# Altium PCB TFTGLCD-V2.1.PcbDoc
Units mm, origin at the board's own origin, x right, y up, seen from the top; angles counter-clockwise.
Board outline 98 x 57 mm, 2 copper layers (Top Layer, Bottom Layer), stack 1.571 mm thick; 48 components, 66 nets, 277 pads, 54 vias.
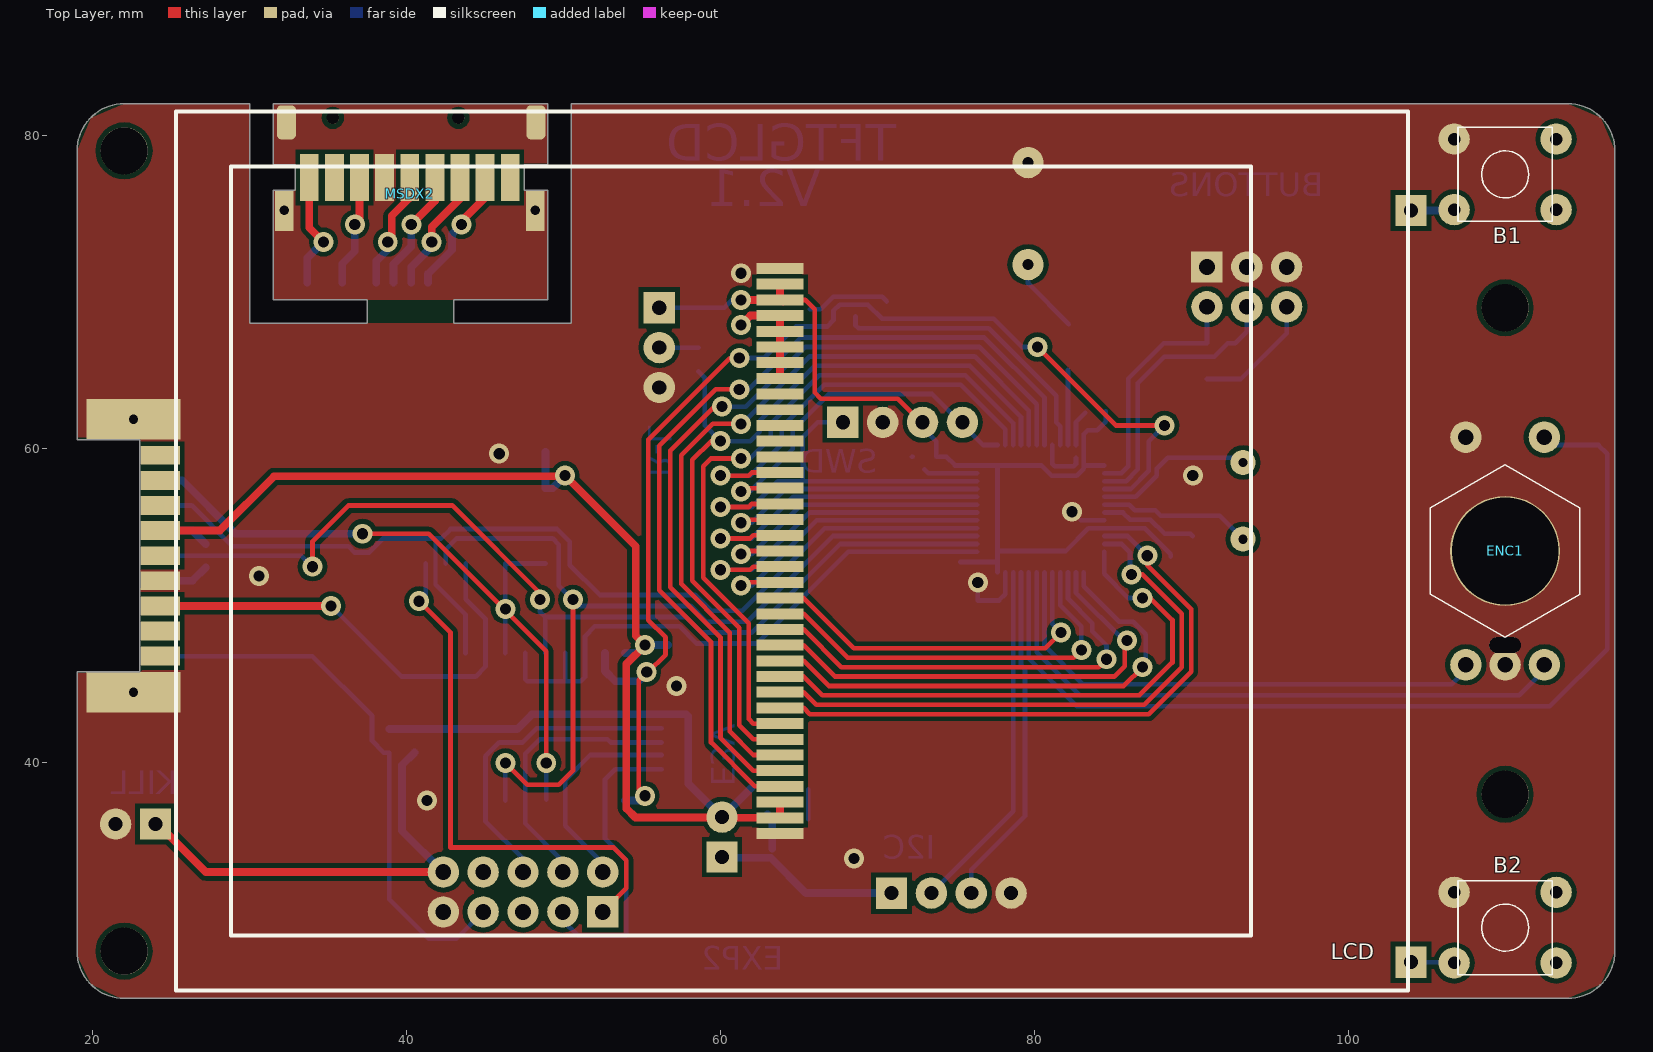
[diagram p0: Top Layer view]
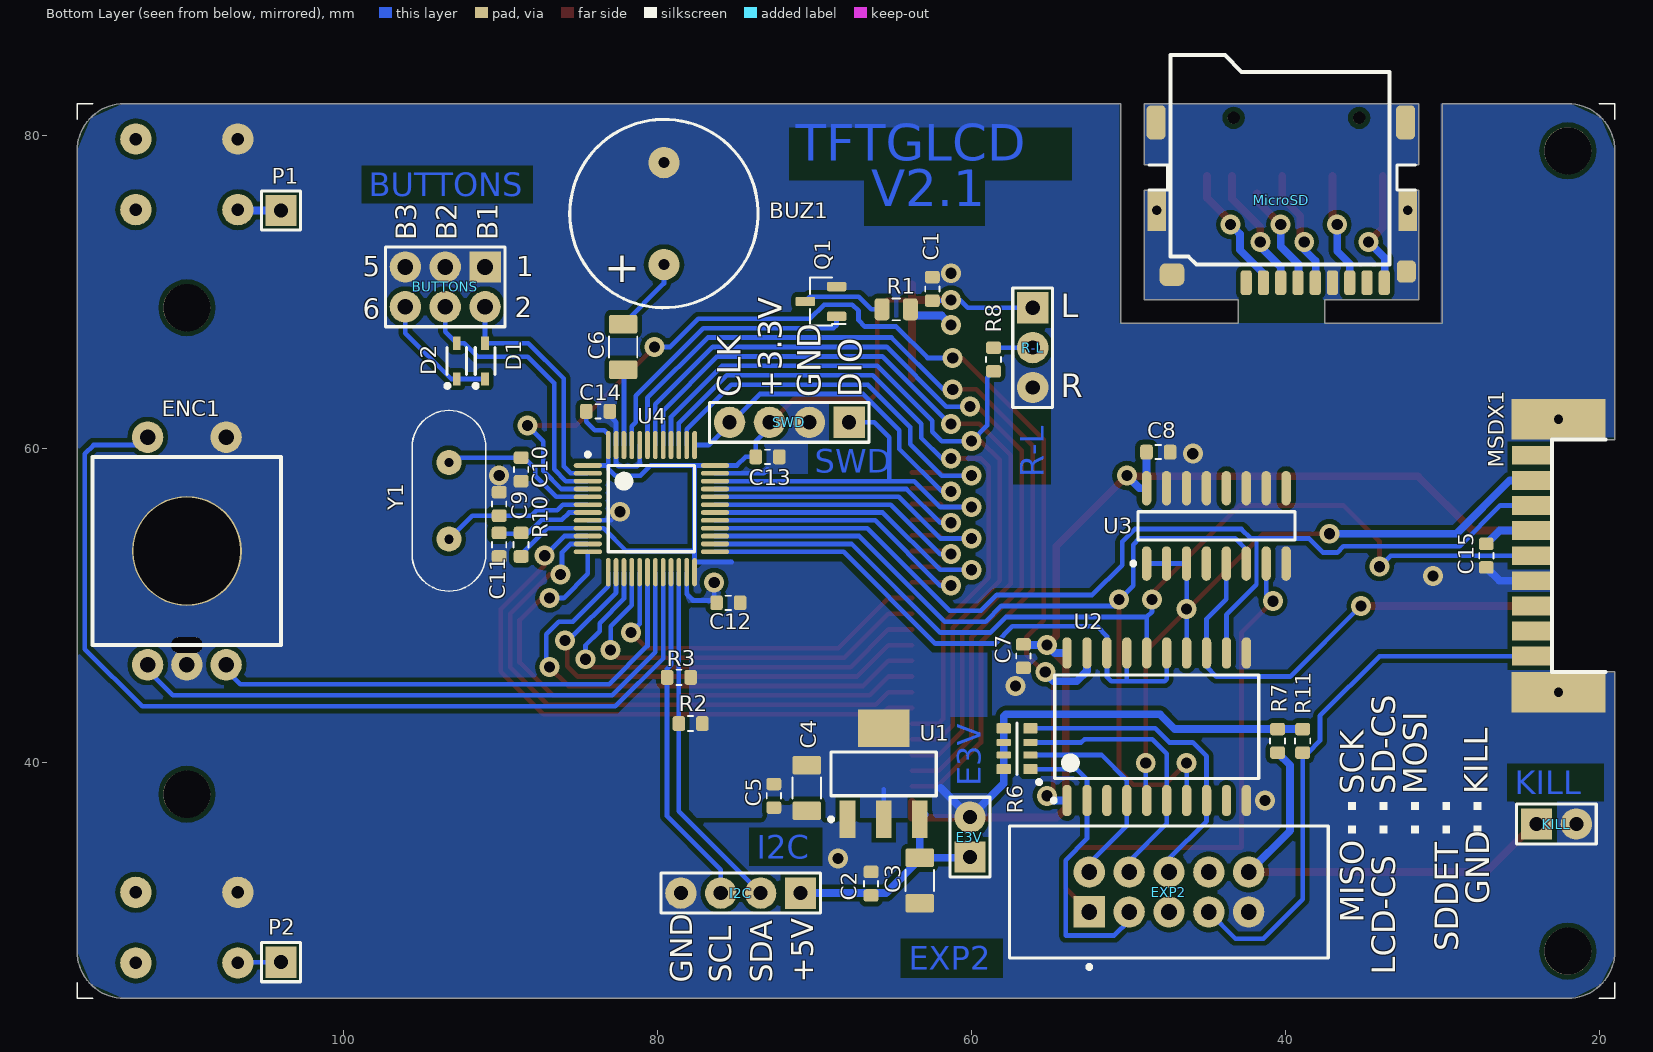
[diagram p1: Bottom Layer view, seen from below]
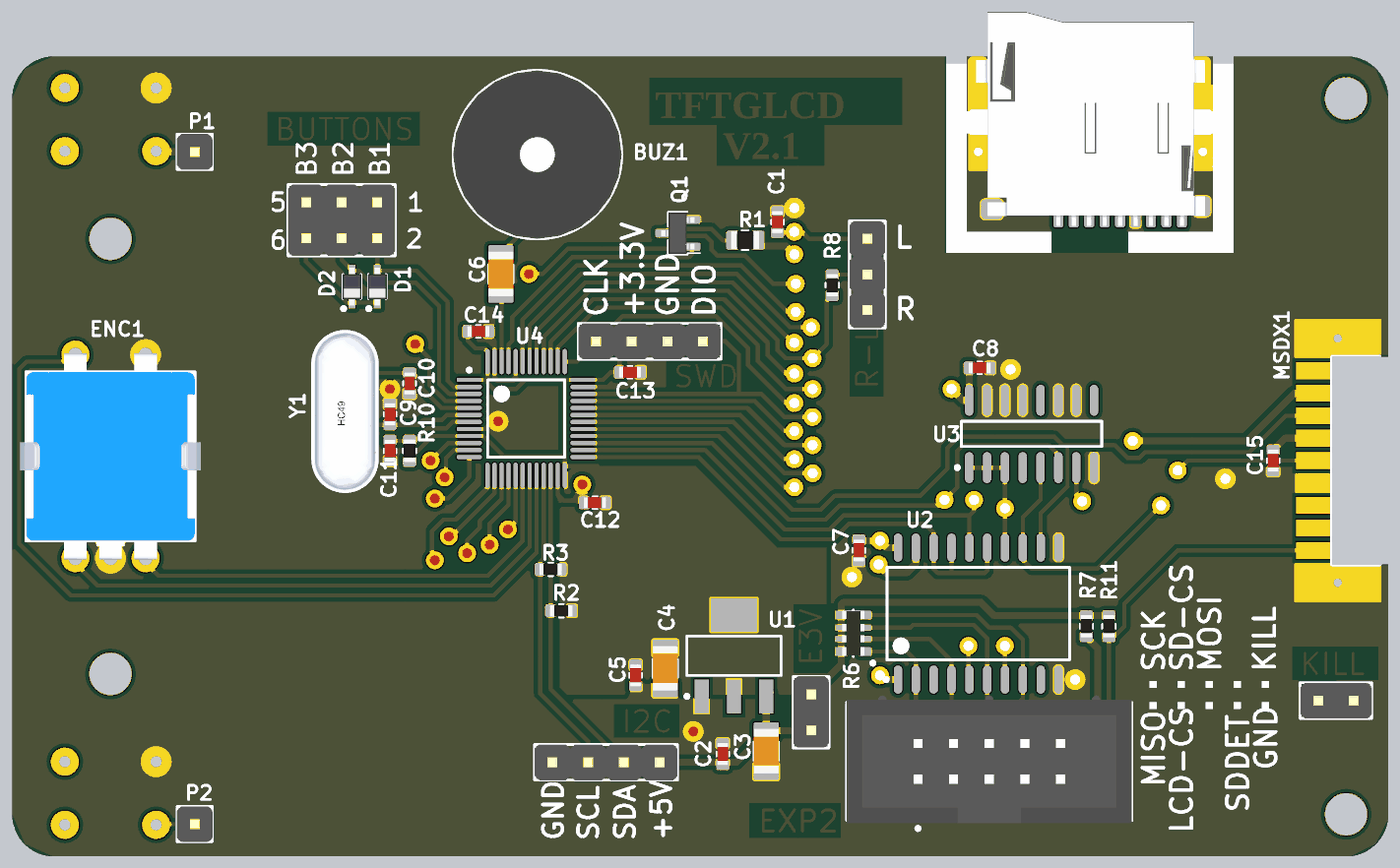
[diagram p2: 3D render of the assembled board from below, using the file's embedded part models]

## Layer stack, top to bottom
Top Layer: signal copper 0.0356
Dielectric: core 1.5, FR-4, Dk 4.8
Bottom Layer: signal copper 0.0356

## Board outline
19,28 19,45.8 23,45.8 23,60.6 19,60.6 19,79 cw(c22,79) 22,82 30,82 30,68 37.5,68 37.5,69.5 31.5,69.5 31.5,76.5 32.9,76.5 32.9,78.1 31.5,78.1 31.5,82 49,82 49,78.1 47.5,78.1 47.5,76.5 49,76.5 49,69.5 43,69.5 43,68 50.5,68 50.5,82 114,82 cw(c114,79) 117,79 117,28 cw(c114,28) 114,25 22,25 cw(c22,28)

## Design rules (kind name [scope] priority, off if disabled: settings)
Clearance Clearance_1 [InPolygon] p1: gap=0.3
Clearance [All] p2: gap=0.2
ComponentClearance [All] p1 off: gap=0.254 collisioncheckmode=3 verticalgap=0.254 showdistances=FALSE
FabricationTestPointUsage [All] p1 off: valid=0 allowmultiple=FALSE
FabricationTestpoint [All] p1 off: side=3 testpointundercomponent=TRUE minsize=1.016 maxsize=2.54 preferedsize=1.524 minholesize=0 maxholesize=1.016 preferedholesize=0.813 testpointgrid=0.025 allowsidetop=TRUE allowsidebottom=TRUE usegrid=TRUE gridtolerance=0
FanoutControl Fanout_BGA [IsBGA] p1 off: bgadir=Out bgaviamode=Centered fanoutstyle=Auto fanoutdirection=Alternating viagrid=0.025 // Fanout_BGA (Default Rule)
FanoutControl Fanout_LCC [IsLCC] p2 off: bgadir=Out bgaviamode=Centered fanoutstyle=Auto fanoutdirection=Alternating viagrid=0.025 // Fanout_LCC (Default Rule)
FanoutControl Fanout_SOIC [IsSOIC] p3 off: bgadir=Out bgaviamode=Centered fanoutstyle=Auto fanoutdirection=Alternating viagrid=0.025 // Fanout_SOIC (Default Rule)
FanoutControl Fanout_Small [(CompPinCount < 5)] p4 off: bgadir=Out bgaviamode=Centered fanoutstyle=Auto fanoutdirection=OutThenIn viagrid=0.025 // Fanout_Small (Default Rule)
FanoutControl Fanout_Default [All] p5 off: bgadir=Out bgaviamode=Centered fanoutstyle=Auto fanoutdirection=Alternating viagrid=0.025 // Fanout_Default (Default Rule)
PolygonConnect [All] p1: connectstyle=Relief reliefconductorwidth=0.5 reliefentries=4 polygonreliefangle="90 Angle" airgapwidth=-0.1
RoutingVias [All] p1: holewidth=0.711 width=1.27 viastyle="Through Hole" minholewidth=0.711 minwidth=1.27 maxholewidth=0.711 maxwidth=1.27
SilkToSilkClearance [All] p1 off: silktosilkclearance=0.254
SilkscreenOverComponentPads [IsPad] p1 off: minsilkscreentomaskgap=0.254
SolderMaskExpansion [All] p1: expansion=0.1
Width [All] p1: maxlimit=2 minlimit=0.2 preferedwidth=0.3
18 further rules are at their usual default settings.

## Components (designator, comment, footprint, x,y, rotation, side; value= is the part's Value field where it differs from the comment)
B1 "SWT-2-x" SWT-2-x 110,77.5 r0 top
B2 "SWT-2-x" SWT-2-x 110,29.5 r0 top
BUTTONS "Header 3X2" HDR2X3 91,71.6 r0 bottom
BUZ1 "Buzer 1205" Buzer_12xx 79.6,75 r90 bottom
C1 "Cap" C0603_Samsung 62.5,70.2 r270 bottom
C2 "Cap" C0603_Samsung 66.4,32.3 r270 bottom
C3 "Cap" C1206_Murata 63.3,32.5 r90 bottom
C4 "Cap" C1206_Murata 70.5,38.4 r90 bottom
C5 "Cap" C0603_Samsung 72.6,37.9 r90 bottom
C6 "Cap" C1206_Murata 82.2,66.5 r270 bottom
C7 "Cap" C0603_Samsung 56.7,46.8 r90 bottom
C8 "Cap" C0603_Samsung 48.1,59.8 r0 bottom
C9 "Cap" C0603_Samsung 90.1,56.5 r270 bottom
C10 "Cap" C0603_Samsung 88.7,58.7 r90 bottom
C11 "Cap" C0603_Samsung 90.1,53.9 r90 bottom
C12 "Cap" C0603_Samsung 75.5,50.2 r180 bottom
C13 "Cap" C0603_Samsung 73,59.5 r0 bottom
C14 "Cap" C0603_Samsung 83.8,62.4 r0 bottom
C15 "Cap" C0603_Samsung 27.2,53.2 r90 bottom
D1 "D_Schottky" SOD323FL_NXP 91,65.6 r90 bottom
D2 "D_Schottky" SOD323FL_NXP 92.8,65.6 r90 bottom
E3V "Header 2" HDR1X2 60.1,34 r90 bottom
ENC1 "Encoder EC-11" Encoder_bot 110,53.5 r0 top
EXP2 "HEADER 2X5_BH10" BH-10 52.5,30.5 r180 bottom
I2C "Header 4" HDR1X4 70.9,31.7 r0 bottom
KILL "Header 2" HDR1X2 24,36.1 r180 bottom
LCD "ILI9325" LCD_ILI9325-37pin 63.8,35.5 r0 top locked
MicroSD "Micro SD" TFP09-2-12B 42.5,70.6 r180 bottom
MSDX1 "CrossPCB-MicroSD" CrossPCB-MicroSD-MB 24.3,59.6 r270 bottom locked
MSDX2 "CrossPCB-MicroSD" CrossPCB-MicroSD-SD 46.6,77.3 r180 bottom
P1 "Plug" PLS-1x1 104,75.2 r180 bottom
P2 "Plug" PLS-1x1 104,27.3 r180 bottom
Q1 "IRLML6344" SOT23-3_IR 69.6,69.4 r0 bottom
R1 "R" R0805_UniOhm 64.8,68.9 r0 bottom
R2 "R" R0603_UniOhm 77.9,42.5 r180 bottom
R3 "R" R0603_UniOhm 78.65,45.45 r180 bottom
R6 "array_r_x4s" RES_Array_ROHM_MNR14 57.1,40.9 r0 bottom
R7 "R" R0603_UniOhm 40.5,41.4 r270 bottom
R8 "R" R0603_UniOhm 58.6,65.7 r90 bottom
R10 "R" R0603_UniOhm 88.7,53.9 r90 bottom
R11 "R" R0603_UniOhm 38.9,41.4 r90 bottom
R-L "Header 3" HDR1X3 56.1,69 r270 bottom
SWD "Header 4" HDR1X4 67.8,61.7 r0 bottom
U1 "LM1117IMP-3.3" MP04A_N 65.6,39.3 r90 bottom
U2 "74LVC241" 751D-03_N 48.2,42.3 r90 bottom
U3 "74HC157" SO16_N 44.4,55.1 r90 bottom
U4 "STM32F103C8T6" LQFP48_N 80.4,56.2 r180 bottom
Y1 "XTAL" XTAL_HC-49_SS3 93.3,56.7 r90 bottom

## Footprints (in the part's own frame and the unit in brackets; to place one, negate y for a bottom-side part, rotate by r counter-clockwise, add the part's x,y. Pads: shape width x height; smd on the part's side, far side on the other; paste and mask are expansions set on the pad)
751D-03_N [mm] "20-Pin Small Outline Integrated Circuit 1.27 mm Pitch, IPC Medium Density"
  oval 2x0.6 smd: 1(-4.7,5.715) 2(-4.7,4.445) 3(-4.7,3.175) 4(-4.7,1.905) 5(-4.7,0.635) 6(-4.7,-0.635) 7(-4.7,-1.905) 8(-4.7,-3.175) 9(-4.7,-4.445) 10(-4.7,-5.715) 11(4.7,-5.715) 12(4.7,-4.445) 13(4.7,-3.175) 14(4.7,-1.905) 15(4.7,-0.635) 16(4.7,0.635) 17(4.7,1.905) 18(4.7,3.175) 19(4.7,4.445) 20(4.7,5.715)
  silkscreen extent -4.82,-6.5 3.3,6.69, body extent -3.8,-6.5 3.8,6.5, height 2.65
BH-10 [mm] "Shrouded Header,vertical,2.54mm pitch;1.00mm lead width,10 pins,2 rows,5 pins per row,20.30mm L X 8.40mm W X 9.30mm H body"
  rect 2x2 hole 1: 1(0,0)
  round 2 hole 1: 2(0,2.54) 3(2.54,0) 4(2.54,2.54) 5(5.08,0) 6(5.08,2.54) 7(7.62,0) 8(7.62,2.54) 9(10.16,0) 10(10.16,2.54)
  silkscreen extent -5.07,-3.63 15.23,5.47, body extent -5.07,-3.13 15.23,5.97, height 9.3
Buzer_12xx [mm]
  round 2 hole 0.7: 1(-3.25,0) 2(3.25,0)
  silkscreen extent -6,-6 6,6, body extent -5.95,-5.99 6,5.99, height 9.5
C0603_Samsung [mm] "Capacitor, Chip; 1.60 mm L X 0.80 mm W X 0.90 mm H body"
  rrect40% 0.8x0.95 smd paste-0.025 mask+0.05: 1(-0.75,0) 2(0.75,0)
  silkscreen extent -0.17,-0.45 0.17,0.45, body extent -0.8,-0.4 0.8,0.4, height 0.9
C1206_Murata [mm] "Capacitor, Chip; 3.20 mm L X 1.60 mm W X 1.80 mm H body"
  rrect20% 1.2x1.8 smd: 1(-1.45,0) 2(1.45,0)
  silkscreen extent -0.67,-0.9 0.67,0.9, body extent -1.6,-0.9 1.6,0.9, height 1.6
CrossPCB-MicroSD-MB [mm] "MicroSD CrossPCB connector MB side"
  rect 1.2x2.5 all layers, no hole: 1(0,0) 2(1.6,0) 3(3.2,0) 4(4.8,0) 5(6.4,0) 6(8,0) 7(9.6,0) 8(11.2,0) 9(12.8,0)
  rect 2.6x6 hole 0.6: 10(-2.3,1.7) 10(15.1,1.7)
  silkscreen extent -1,1.3 13.8,4.7
CrossPCB-MicroSD-SD [mm] "MicroSD CrossPCB connector SD side"
  rect 1.2x3 smd far side: 1(0,0) 2(1.6,0) 3(3.2,0) 4(4.8,0) 5(6.4,0) 6(8,0) 7(9.6,0) 8(11.2,0) 9(12.8,0)
  rect 1.2x2.6 hole 0.6: 10(-1.6,-2.1) 10(14.4,-2.1)
  silkscreen extent -2.1,-0.8 14.9,0.8
Encoder_bot [mm]
  oval 2x1 hole 1 slot 2 at 0 deg: 0(0,-6)
  round 7 hole 6.8: 0(0,0)
  round 2 hole 1: 1(-2.5,-7.25) 2(0,-7.25) 3(2.5,-7.25) 4(-2.5,7.25) 5(2.5,7.25)
  silkscreen extent -4.76,-5.5 4.76,5.5, body extent -6.43,-7.35 6.43,7.35, height 13.5
HDR1X2 [mm] "Connector; Header; 2 Position"
  rect 2x2 hole 0.9: 1(0,0)
  round 2 hole 0.9: 2(2.54,0)
  silkscreen extent -1.27,-1.27 3.81,1.27, body extent -1.25,-1.27 3.83,1.27, height 9
HDR1X3 [mm] "Connector; Header; 3 Position"
  rect 2x2 hole 0.9: 1(0,0)
  round 2 hole 0.9: 2(2.54,0) 3(5.08,0)
  silkscreen extent -1.27,-1.27 6.35,1.27, body extent -1.27,-1.27 6.35,1.27, height 9
HDR1X4 [mm] "Connector; Header; 4 Position"
  rect 2x2 hole 0.9: 1(0,0)
  round 2 hole 0.9: 2(2.54,0) 3(5.08,0) 4(7.62,0)
  silkscreen extent -1.27,-1.27 8.89,1.27, body extent -1.27,-1.27 8.89,1.27, height 9
HDR2X3 [mm] "Connector; Header; 3x2 Position"
  rect 2x2 hole 1: 1(0,0)
  round 2 hole 1: 2(0,2.54) 3(2.54,0) 4(2.54,2.54) 5(5.08,0) 6(5.08,2.54)
  silkscreen extent -1.27,-1.27 6.35,3.81, body extent -1.27,-1.27 6.35,3.81, height 9
LCD_ILI9325-37pin [mm]
  rect 3x0.7 smd: 1(0,0) 2(0,1) 3(0,2) 4(0,3) 5(0,4) 6(0,5) 7(0,6) 8(0,7) 9(0,8) 10(0,9) 11(0,10) 12(0,11) 13(0,12) 14(0,13) 15(0,14) 16(0,15) 17(0,16) 18(0,17) 19(0,18) 20(0,19) 21(0,20) 22(0,21) 23(0,22) 24(0,23) 25(0,24) 26(0,25) 27(0,26) 28(0,27) 29(0,28) 30(0,29) 31(0,30) 32(0,31) 33(0,32) 34(0,33) 35(0,34) 36(0,35) 37(0,36)
  silkscreen extent -38.5,-10 40,46, body extent -38.5,-10 40.1,46, height 3
LQFP48_N [mm] "Thin QFP, 48-Leads, Body 7x7mm, Pitch 0.5mm, IPC Medium Density"
  oval 1.8x0.3 smd: 1(-4.05,2.75) 2(-4.05,2.25) 3(-4.05,1.75) 4(-4.05,1.25) 5(-4.05,0.75) 6(-4.05,0.25) 7(-4.05,-0.25) 8(-4.05,-0.75) 9(-4.05,-1.25) 10(-4.05,-1.75) 11(-4.05,-2.25) 12(-4.05,-2.75) 25(4.05,-2.75) 26(4.05,-2.25) 27(4.05,-1.75) 28(4.05,-1.25) 29(4.05,-0.75) 30(4.05,-0.25) 31(4.05,0.25) 32(4.05,0.75) 33(4.05,1.25) 34(4.05,1.75) 35(4.05,2.25) 36(4.05,2.75)
  oval 0.3x1.8 smd: 13(-2.75,-4.05) 14(-2.25,-4.05) 15(-1.75,-4.05) 16(-1.25,-4.05) 17(-0.75,-4.05) 18(-0.25,-4.05) 19(0.25,-4.05) 20(0.75,-4.05) 21(1.25,-4.05) 22(1.75,-4.05) 23(2.25,-4.05) 24(2.75,-4.05) 37(2.75,4.05) 38(2.25,4.05) 39(1.75,4.05) 40(1.25,4.05) 41(0.75,4.05) 42(0.25,4.05) 43(-0.25,4.05) 44(-0.75,4.05) 45(-1.25,4.05) 46(-1.75,4.05) 47(-2.25,4.05) 48(-2.75,4.05)
  silkscreen extent -4.18,-2.75 2.75,3.57, body extent -3.5,-3.5 3.5,3.5, height 1.6
MP04A_N [mm] "SOT223, 4-Leads, Body 6.5x3.5mm, Pitch 2.3mm, Lead Span 7mm, IPC Medium Density"
  rect 2.4x1 smd: 1(-2.9,2.3) 2(-2.9,0) 3(-2.9,-2.3)
  rect 2.4x3.3 smd: 4(2.9,0)
  silkscreen extent -3.02,-3.35 1.4,3.48, body extent -1.85,-3.35 1.85,3.35, height 1.8
PLS-1x1 [mm]
  rect 2x2 hole 0.9: 1(0,0)
  silkscreen extent -1.25,-1.25 1.25,1.25, body extent -1.27,-1.27 1.27,1.27, height 9
R0603_UniOhm [mm] "Resistor, Chip; 1.60 mm L X 0.825 mm W X 0.55 mm H body"
  rrect40% 0.8x0.95 smd paste-0.025 mask+0.05: 1(-0.75,0) 2(0.75,0)
  silkscreen extent -0.17,-0.48 0.17,0.48, body extent -0.8,-0.41 0.8,0.41, height 0.55
R0805_UniOhm [mm] "Resistor, Chip; 2.00 mm L X 1.275 mm W X 0.65 mm H body"
  rrect40% 0.95x1.4 smd paste-0.025 mask+0.05: 1(-0.9,0) 2(0.9,0)
  silkscreen extent -0.25,-0.7 0.25,0.7, body extent -1,-0.64 1,0.64, height 0.65
RES_Array_ROHM_MNR14 [mm] "Resistor,Chip Array,0.80mm pitch;8 pin,1.60mm W X 3.20mm L X 0.60mm H, Convex"
  rrect15% 0.9x0.65 smd paste-0.025 mask+0.05: 1(-0.85,1.3) 4(-0.85,-1.3) 5(0.85,-1.3) 8(0.85,1.3)
  rrect22% 0.9x0.45 smd paste-0.025 mask+0.05: 2(-0.85,0.4) 3(-0.85,-0.4) 6(0.85,-0.4) 7(0.85,0.4)
  silkscreen extent -1.52,-1.65 0,2.25, body extent -0.8,-1.6 0.8,1.6, height 0.55
SO16_N [mm] "SOIC, 16-Leads, Body 9.9x3.9mm, Pitch 1.27mm, IPC Medium Density"
  oval 2.2x0.6 smd: 1(-2.4,4.445) 2(-2.4,3.175) 3(-2.4,1.905) 4(-2.4,0.635) 5(-2.4,-0.635) 6(-2.4,-1.905) 7(-2.4,-3.175) 8(-2.4,-4.445) 9(2.4,-4.445) 10(2.4,-3.175) 11(2.4,-1.905) 12(2.4,-0.635) 13(2.4,0.635) 14(2.4,1.905) 15(2.4,3.175) 16(2.4,4.445)
  silkscreen extent -2.52,-5 0.9,5.42, body extent -1.95,-4.95 1.95,4.95, height 1.75
SOD323FL_NXP [mm] "SODFL Diode;1.80mm W X 1.35mm L X 0.80mm H body"
  rrect10% 0.85x0.5 smd paste-0.025 mask+0.05: A(1.14,0) C(-1.14,0)
  silkscreen extent -1.7,-0.63 0.85,0.73, body extent -1.35,-0.67 1.35,0.68, height 0.79
SOT23-3_IR [mm] "Small Outline Transistor (SOT23), 0.95 mm pitch; 3 pin, 2.92 mm L X 1.30 mm W X 1.12 mm H body"
  rrect40% 1.25x0.6 smd paste-0.025 mask+0.05: 1(-1,0.95) 2(-1,-0.95) 3(1,0)
  silkscreen extent -1.57,-1.52 0.7,1.52, body extent -1.18,-1.46 1.18,1.46, height 1.12
SWT-2-x [mm] "Button"
  round 2 hole 0.8: 1(-3.25,2.25) 2(-3.25,-2.25) 3(3.25,-2.25) 4(3.25,2.25)
  silkscreen extent -3,-3 3,3
TFP09-2-12B [mil] "http://ali.pub/2rgdx8"
  round 30 hole 31.5 mask+0: 0(-31.5,413.39) 0(283.46,413.39)
  rrect50% 28x62 smd: 1(0,0) 2(43.31,0) 3(86.61,0) 4(129.92,0) 5(173.23,0) 6(216.54,0) 7(259.84,0) 8(303.15,0) 9(346.46,0)
  rrect50% 48x56 smd: 10(402,28)
  rrect50% 62x56 smd: 11(-186,20)
  rrect50% 48x86 all layers, no hole: 12(-226,402) 12(400,402)
  silkscreen extent -190,45 360,571, body extent -230,-27 412,572, height 79
XTAL_HC-49_SS3 [mm] "Quartz"
  round 1.6 hole 0.6: 1(-2.438,0) 2(2.438,0)
  silkscreen extent -5.76,-2.35 5.76,2.35, body extent -5.75,-2.32 5.75,2.33, height 3.5

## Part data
BUTTONS: "Header, 3-Pin, Dual row"
BUZ1: library part Buzer
C1 C2 C5 C7 C8 C11 C12 C13 C14 C15: library part CL10B104KB8NNNC
C3 C4 C6: library part GRM31CR71H475KA12L
C9 C10: library part CL10C220JB8NNNC
D1 D2: library part PMEG6010CEJ,115, "60V, 1A, very low VF MEGA Schottky barrier rectifiers"
E3V KILL: "Header, 2-Pin"
ENC1: library part Encoder, "Rotary Encoder with button"
EXP2: library part BH-10, "IDC-10M Connector (BH-10)"
I2C SWD: "Header, 4-Pin"
LCD: library part LCD_ILI9325-37pin
MicroSD: library part TFP09-2-12B
MSDX1 MSDX2: "Micro SD CrossPCB connector"
Q1: library part IRLML6344TRPBF, "30 V, 5.0 A, 0.029 Ohm Single N-Channel HEXFET Power MOSFET"
R1: library part 0805S8F4700T50
R2 R3 R7 R8 R10 R11: library part 0603SAF1002T50
R6: library part MNR14ERAPJ103, "4x Chip Array Convex"
R-L: "Header, 3-Pin"
U1: "800mA Low-Dropout Linear Regulator"
U3: library part 74LVQ157M, "Low-Voltage Quad 2-Channel Multiplexer"
U4: "STM32 ARM-based 32-bit MCU with 64 Kbytes Flash, 48-pin LQFP, Industrial Temperature"
Y1: library part "KX-3HT 10.0MHZ", "10MHz Quartz HC49"

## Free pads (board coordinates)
  round 3 hole 3: 1(22,28) 1(22,79) 1(110,38) 1(110,69)

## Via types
v1: diameter 1.27, hole 0.711, Top Layer to Bottom Layer, 54 vias

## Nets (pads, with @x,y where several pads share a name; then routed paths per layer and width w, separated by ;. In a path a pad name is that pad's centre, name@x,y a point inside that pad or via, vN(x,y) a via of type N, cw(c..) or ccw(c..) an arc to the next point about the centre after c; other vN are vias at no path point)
+3.3V: C1.2 C4.2 C5.2 C7.2 C8.2 C12.2 C13.2 C14.2 C15.2 E3V.2 LCD.2 LCD.3 LCD.35 LCD.36 MSDX1.4 R2.2 R3.2 R6.5 R6.6 R6.7 R6.8 R7.1 R10.1 R11.2 R-L.1 SWD.3 U1.2 U1.4 U2.20 U3.16 U4.1 U4.9 U4.24 U4.36 U4.48 | length 169.1
  Top Layer w0.3: LCD.35@64,69.3 64.2,69.5 65.4,69.5 66,68.9 66,63.6 66.4,63.2 71.3,63.2 SWD.3@72.79,61.71
  Top Layer w0.5: MSDX1.4 28.1,54.8 31.559,58.259 50.141,58.259 54.6,53.8 54.6,48.1 v1(55.2,47.5) 54,46.3 54,37.1 54.585,36.515 60.075,36.515 E3V.2 ; E3V.2@60.2,36.5 LCD.2 LCD.3 ; v1(61.3,69.5) LCD.35 LCD.36
  Bottom Layer w0.3: R-L.1 60.25,69 60.75,69.5 v1(61.3,69.5) ; v1@61.25,69.45 C1.2 C1.2@62.45,69.4 ; U1.2 65.6,38.3 ; SWD.3@72.54,61.7 73.75,60.49 C13.2 74.4,59.5 74.95,58.95 U4.36 77.65,58.95 ; 75.3,52.8 U4.24@77.65,52.8 ; U4.24 77.65,53.5 ; U4.1 83.15,58.95 ; C14.2 84.55,61.75 84,61.2 83.4,61.2 83.15,60.95 U4.48 83.15,58.95 ; R10.1 88.7,53.3 87.05,54.95 U4.9 83.45,54.95 82,53.5 77.65,53.5 ; 77.65,53.5 77.65,58.95 ; 77.65,58.95 80.45,58.95 81.1,58.3 82.7,58.3 83.15,58.75 83.15,58.95
  Bottom Layer w0.5: MSDX1.4 26.35,54.8 C15.2 ; R11.2 R7.1 47.05,42.15 48,43.1 57.8,43.1 57.95,42.95 R6.5 R6.6 R6.7 R6.8 57.95,38.69 E3V.2 61.96,38.4 ; U3.16 49.3,57.5 v1(50.1,58.3) ; U3.16@48.85,57.505 C8.2 ; U2.20 54.7,47 v1(55.2,47.5) C7.2@56.65,47.5
+5V: C2.2 C3.2 E3V.1 I2C.1 U1.3 | length 14
  Bottom Layer w0.5: E3V.1@60.15,33.95 63.2,33.95 65.45,31.7 I2C.1 ; U1.3@63,36.7 U1.3 63.3,34.55
B1: BUTTONS.2 D1.A U4.2 | length 15.6
  Bottom Layer w0.3: U4.2 85.55,58.45 85.99,58.89 85.99,64.491 88.239,66.74 D1.A BUTTONS.2
B2: BUTTONS.4 D2.A U4.3 | length 17.8
  Bottom Layer w0.3: U4.3 85.85,57.95 86.6,58.7 86.6,64.2 88.276,65.876 91.457,65.876 92.321,66.74 D2.A 93.54,67.48 BUTTONS.4
BEEP: C6.2 U4.46 | length 4.8
  Bottom Layer w0.3: U4.46 C6.2@82.15,65.05
BOOTSD: U2.1 U2.19 U4.4 | length 76.8
  Top Layer w0.3: v1(55.2,37.9) 54.8,38.3 54.8,45.3 v1(55.3,45.8) ; v1@55.35,45.75 56.5,46.9 56.5,48 55.4,49.1 55.4,60.6 60.55,65.75 61.15,65.75 v1(61.2,65.8) ; v1(80.2,66.5) 85.2,61.5 v1(88.3,61.5)
  Bottom Layer w0.3: v1(61.2,65.8) 62.8,65.8 64.8,67.8 66.8,67.8 67.2,68.2 67.2,68.8 67.6,69.2 69.4,69.2 70.3,68.3 77.4,68.3 79.2,66.5 v1(80.2,66.5) ; U4.4 86.15,57.45 87.3,58.6 87.3,60.5 v1(88.3,61.5)
  Bottom Layer w0.5: U2.19 52.645,45.855 53.3,45.2 54.787,45.2 55.343,45.757 v1(55.3,45.8) ; U2.1 55.3,37.6 55.2,37.7 v1(55.2,37.9)
BRIGHTNES: Q1.1 U4.45 | length 18.5
  Bottom Layer w0.3: Q1.1 68.6,67.9 68.8,67.7 77.1,67.7 81.4,63.4 81.4,61.7 81.65,61.45 U4.45
BTNEN2: EXP2.5
CS-: LCD.4 U4.43 | length 57.8
  Top Layer w0.3: v1(61.2,63.8) 59.7,63.8 56.1,60.2 56.1,51 59.4,47.7 59.4,41.3 62.2,38.5 LCD.4
  Bottom Layer w0.3: v1(61.2,63.8) 61.8,63.8 65.1,67.1 76.8,67.1 80.65,63.25 U4.43
CS-LCD: U2.15 U2.17 U2.18 U4.25 | length 38.2
  Bottom Layer w0.3: U2.15 47.565,45.335 47.7,45.2 50.105,45.2 ; U2.17 50.105,45.2 ; U4.25 68.15,53.45 62.3,47.6 58.5,47.6 57.4,48.7 52,48.7 51.375,48.075 U2.18 51.375,45.475 51.1,45.2 50.105,45.2
CS-SD: MSDX1.2 U2.5 U2.14 U3.1 U3.2 U3.3 | length 46.3
  Top Layer w0.3: v1@37.761,54.6 41.4,54.6 48.9,47.1 v1(48.9,40)
  Top Layer w0.5: v1(37.2,54.6) v1@37.257,54.6
  Bottom Layer w0.3: U2.14 U3.3@46.295,52.7 ; U3.3 U3.2 U3.1 ; U2.5@48.9,37.665 v1(48.9,40)
  Bottom Layer w0.5: MSDX1.2 25.7,58 29.1,54.6 v1(37.2,54.6)
  other v1: 46.295,49.8
D0: LCD.9 U4.10 | length 39.7
  Top Layer w0.3: LCD.9 65.3,43.5 65.7,43.1 87.3,43.1 90,45.8 90,49.8 87.2,52.6 v1(87.2,53.2)
  Bottom Layer w0.3: U4.10 85.95,54.45 v1(87.2,53.2) v1@87.45,52.95
D1: LCD.10 U4.11 | length 37.9
  Top Layer w0.3: LCD.10 65.3,44.5 66.1,43.7 87,43.7 89.4,46.1 89.4,49.5 86.9,52 v1@86.1,52
  Bottom Layer w0.3: U4.11 85.55,53.95 86.1,53.4 v1@86.1,52
  other v1: 86.2,52
D2: LCD.11 U4.12 | length 36
  Top Layer w0.3: LCD.11 65.3,45.5 66.5,44.3 86.7,44.3 88.8,46.4 88.8,49.1 87.4,50.5 v1(86.9,50.5)
  Bottom Layer w0.3: U4.12 84.45,52.05 86,50.5 v1(86.9,50.5)
D3: LCD.12 U4.13 | length 32.6
  Top Layer w0.3: LCD.12 65.3,46.5 66.9,44.9 85.7,44.9 v1(86.9,46.1)
  Bottom Layer w0.3: U4.13 83.15,51.25 85.4,49 86.3,49 87.1,48.2 87.1,46.3 v1(86.9,46.1)
D4: LCD.13 U4.14 | length 30.6
  Top Layer w0.3: LCD.13 65.3,47.5 67.3,45.5 85.1,45.5 85.769,46.169 85.769,47.669 v1(85.9,47.8)
  Bottom Layer w0.3: U4.14 82.65,50.85 85.693,47.807 v1@85.9,47.807
D5: LCD.14 U4.15 | length 28.6
  Top Layer w0.3: LCD.14 65.3,48.5 67.7,46.1 84.1,46.1 v1(84.6,46.6)
  Bottom Layer w0.3: U4.15 82.15,50.45 83.7,48.9 83.7,48.4 84.6,47.5 v1(84.6,46.6)
D6: LCD.15 U4.16 | length 26.1
  Top Layer w0.3: LCD.15 65.3,49.5 68.1,46.7 82.5,46.7 v1(83,47.2)
  Bottom Layer w0.3: U4.16 81.65,50.05 83,48.7 v1(83,47.2)
D7: LCD.16 U4.17 | length 23.7
  Top Layer w0.3: LCD.16 65.3,50.5 68.5,47.3 80.7,47.3 v1(81.7,48.3)
  Bottom Layer w0.3: U4.17 81.15,48.85 v1(81.7,48.3)
D8: LCD.17 U4.29 | length 19.4
  Top Layer w0.3: v1(61.3,51.3) 61.5,51.5 LCD.17
  Bottom Layer w0.3: v1(61.3,51.3) 62,51.3 66.15,55.45 U4.29
D9: LCD.18 U4.30 | length 21.7
  Top Layer w0.3: v1(60,52.3) 61.9,52.3 62.1,52.5 LCD.18
  Bottom Layer w0.3: v1(60,52.3) 62,52.3 65.65,55.95 U4.30
D10: LCD.19 U4.31 | length 18.9
  Top Layer w0.3: v1(61.3,53.3) 61.5,53.5 LCD.19
  Bottom Layer w0.3: v1(61.3,53.3) 62,53.3 65.15,56.45 U4.31
D11: LCD.20 U4.32 | length 21.3
  Top Layer w0.3: v1(60,54.3) 61.9,54.3 62.1,54.5 LCD.20
  Bottom Layer w0.3: v1(60,54.3) 62,54.3 64.65,56.95 U4.32
D12: LCD.21 U4.33 | length 18.5
  Top Layer w0.3: v1(61.3,55.3) 61.5,55.5 LCD.21
  Bottom Layer w0.3: v1(61.3,55.3) 62,55.3 64.15,57.45 U4.33
D13: LCD.22 SWD.1 U4.34 | length 26.3
  Top Layer w0.3: v1(60,56.3) 61.8,56.3 62,56.5 LCD.22
  Bottom Layer w0.3: v1(60,56.3) 62,56.3 63.65,57.95 65.25,57.95 ; SWD.1@67.46,61.7 66.2,61.7 65.25,60.75 65.25,57.95 ; U4.34 65.25,57.95
D14: LCD.23 SWD.4 U4.37 | length 23.6
  Top Layer w0.3: v1(61.3,57.3) 61.5,57.5 LCD.23
  Bottom Layer w0.3: v1(61.3,57.3) 61.9,57.3 64.6,60 64.6,61.2 66.9,63.5 73.5,63.5 76.75,60.25 U4.37
D15: LCD.24 U4.38 | length 27.3
  Top Layer w0.3: v1(60,58.3) 61.8,58.3 62,58.5 LCD.24
  Bottom Layer w0.3: v1(60,58.3) 61.9,58.3 63.9,60.3 63.9,61.4 66.6,64.1 75.3,64.1 78.15,61.25 U4.38
ENCA: ENC1.1 U4.18 | length 33.3
  Bottom Layer w0.3: U4.18 80.65,47.45 83.1,45 106.6,45 107.5,45.9 ENC1.1
ENCB: ENC1.3 U4.19 | length 39.6
  Bottom Layer w0.3: U4.19 80.15,47.05 82.9,44.3 110.901,44.3 112.5,45.899 ENC1.3
ENCBT: ENC1.5 U4.20 | length 61.3
  Bottom Layer w0.3: U4.20 79.65,46.65 82.7,43.6 112.851,43.6 116.5,47.249 116.5,59.7 115.95,60.25 ENC1.5@113,60.25
GND: B1.1 B2.1 BUTTONS.1 BUTTONS.3 BUTTONS.5 BUZ1.2 C1.1 C2.1 C3.1 C4.1 C5.1 C7.1 C8.1 C9.1 C10.1 C11.1 C12.1 C13.1 C14.1 C15.1 ENC1.0 ENC1.2 ENC1.4 EXP2.9 I2C.4 KILL.2 LCD.1 LCD.25 LCD.37 MSDX1.6 MSDX1.10 Q1.2 R-L.3 SWD.2 U1.1 U2.10 U2.11 U3.8 U3.10 U3.11 U3.13 U3.14 U3.15 U4.8 U4.23 U4.35 U4.44 U4.47 | length 18.7
  Bottom Layer w0.3: C13.1@72.2,59.5 C13.1 ; 73,58.7 73.25,58.45 U4.35 ; v1(76.4,51.5) 76.4,50.35 77.75,50.35 78.15,50.75 U4.23 ; U4.44 81.15,59.05 81.3,58.9 82.5,58.9 82.65,59.05 U4.47@82.65,59.45 ; U4.47 82.65,61.7 C14.1@83.25,62.3 ; 82.95,55.45 U4.8
  Bottom Layer w0.5: MSDX1.6@23.8,51.6 26.35,51.6 C15.1
  other v1: 68.5,33.9 41.3,37.6 57.2,44.9 30.6,51.9 82.4,56 90.1,58.3 45.9,59.7 61.3,71.2
KILL: EXP2.10 KILL.1 R7.2 | length 28.5
  Top Layer w0.5: KILL.1@24.1,36.1 24.14,36.1 27.2,33.04 EXP2.10
  Bottom Layer w0.5: R7.2 39.7,39.85 39.7,35.68 EXP2.10
LCD-CS: EXP2.3 R6.1 U2.2 | length 19.4
  Bottom Layer w0.3: EXP2.3 49.96,29.94 50.9,29 54,29 54,33.8 52.645,35.155 U2.2 52.645,38.945 53.3,39.6 R6.1
MISO: EXP2.1 U3.7 | length 34.6
  Top Layer w0.3: v1(40.8,50.3) 42.8,48.3 42.8,34.6 53.2,34.6 54,33.8 54,32 EXP2.1
  Bottom Layer w0.3: v1(40.8,50.3) 41.225,50.725 U3.7
MISO-L: U2.7 U3.6 U4.27 | length 59.8
  Top Layer w0.3: v1(46.3,40) 47.7,38.6 49.7,38.6 50.6,39.5 v1(50.6,50.4)
  Bottom Layer w0.3: U3.6 42.495,53.595 43.2,54.3 49.3,54.3 49.7,53.9 49.7,51.3 v1(50.6,50.4) 50.6,50 58.1,50 59.1,49 61.7,49 67.15,54.45 U4.27 ; U2.7 46.295,39.995 v1(46.3,40)
MISO-SD: MSDX1.7 U2.13 U3.5 | length 29.9
  Top Layer w0.5: MSDX1.7 v1(35.183,50)
  Bottom Layer w0.3: v1(35.183,50) 39.683,45.5 44.4,45.5 45.025,46.125 U2.13 45.025,49.175 43.765,50.435 U3.5
MOSI: EXP2.6 R6.4 U2.8 | length 20.3
  Bottom Layer w0.3: EXP2.6 47.42,33.88 45.025,36.275 U2.8 45.025,40.425 45.9,41.3 47.4,41.3 48.3,42.2 R6.4
MOSI-I: MSDX1.3 U2.12 U4.28 | length 67.2
  Bottom Layer w0.25: 41.85,51.35 41.85,54.3
  Bottom Layer w0.3: MSDX1.3 26.3,56.4 28.9,53.8 36.3,53.8 36.7,53.4 37.6,53.4 38.5,54.3 41.8,54.3 ; 41.85,51.35 43.755,49.445 U2.12 ; 41.85,54.3 42.2,54.3 42.8,54.9 49.6,54.9 50.4,54.1 50.4,52.6 52.3,50.7 58.4,50.7 59.4,49.7 61.4,49.7 66.65,54.95 U4.28
NetB1_2: B1.2 P1.1 | length 2.7
  Bottom Layer w0.5: P1.1 B1.2@106.7,75.2
NetB2_2: B2.2 P2.1 | length 2.8
  Bottom Layer w0.3: P2.1 106.7,27.3 B2.2
NetBUTTONS_6: BUTTONS.6 D1.C D2.C | length 8
  Bottom Layer w0.3: D1.C D2.C 93.16,64.46 96.08,67.38 BUTTONS.6
NetBUZ1_1: BUZ1.1 C6.1 | length 4.9
  Bottom Layer w0.3: BUZ1.1 79.6,70.55 C6.1
NetC9_2: C9.2 U4.6 Y1.1 | length 9.8
  Bottom Layer w0.3: U4.6 86.05,56.45 86.4,56.1 87.7,56.1 88.05,55.75 C9.2 91.812,55.75 Y1.1
NetC10_2: C10.2 U4.5 Y1.2 | length 10.3
  Bottom Layer w0.3: U4.5 86.45,56.95 87.8,58.3 87.8,58.751 88.499,59.45 C10.2 92.988,59.45 Y1.2
NetC11_2: C11.2 R10.2 U4.7 | length 6.3
  Bottom Layer w0.3: U4.7 85.65,55.95 86.1,55.5 87.4,55.5 88.3,54.6 89.95,54.6 C11.2@90.1,54.45
NetLCD_30: LCD.30 LCD.31 LCD.32 LCD.33 LCD.34 R1.1 | length 9.3
  Top Layer w0.5: v1(61.3,67.9) 61.9,68.5 LCD.34 LCD.33 LCD.32 LCD.31 LCD.30
  Bottom Layer w0.5: v1(61.3,67.9) 61.9,68.5 R1.1@63.6,68.5
NetMicroSD_2: MicroSD.2 MSDX2.2 | length 8.5
  Top Layer w0.5: v1(43.5,74.3) 43.3,74.3 45,76 MSDX2.2@45,77.4
  Bottom Layer w0.5: MicroSD.2@41.37,70.6 41.37,71.17 42.9,72.7 42.9,73.7 43.2,74 v1@43.2,74.3
NetMicroSD_3: MicroSD.3 MSDX2.3 | length 8.1
  Top Layer w0.5: v1(41.6,73.2) 41.6,74.15 43.4,75.95 MSDX2.3@43.4,77.4
  Bottom Layer w0.5: MicroSD.3 40.3,71.6 41.6,72.9 v1(41.6,73.2)
NetMicroSD_4: MicroSD.4 MSDX2.4 | length 6.8
  Top Layer w0.5: v1(40.3,74.3) 41.8,75.8 MSDX2.4@41.8,76.3
  Bottom Layer w0.5: MicroSD.4@39.17,70.6 39.17,71.77 40.3,72.9 v1(40.3,74.3)
NetMicroSD_5: MicroSD.5 MSDX2.5 | length 7.7
  Top Layer w0.5: v1(38.8,73.2) 39.056,73.456 39.056,74.856 40.2,76 MSDX2.5@40.2,77.4
  Bottom Layer w0.5: MicroSD.5@38.07,70.6 38.07,71.97 38.8,72.7 v1(38.8,73.2)
NetMicroSD_6: MicroSD.6 MicroSD.10 MicroSD.11 MicroSD.12 MSDX2.6 MSDX2.10
NetMicroSD_7: MicroSD.7 MSDX2.7 | length 7.3
  Top Layer w0.5: v1(36.7,74.3) 37,74.6 MSDX2.7@37,77.4
  Bottom Layer w0.5: MicroSD.7 35.9,71.8 36.7,72.6 v1(36.7,74.3)
NetMicroSD_9: MicroSD.9 MSDX2.9 | length 7.6
  Top Layer w0.5: MSDX2.9@33.8,77.4 33.8,74.1 v1(34.7,73.2)
  Bottom Layer w0.5: MicroSD.9@33.67,70.6 33.67,72.17 v1(34.7,73.2)
NetQ1_3: Q1.3 R1.2 | length 5.4
  Bottom Layer w0.3: R1.2 66.4,68.9 67.2,69.7 70.3,69.7 Q1.3
NetR8_2: R8.2 R-L.2 | length 2.5
  Bottom Layer w0.3: R-L.2 R8.2@58.6,66.46
RD-: LCD.7 R8.1 U4.40 | length 53.1
  Top Layer w0.3: v1(60,60.5) 59.4,60.5 58.2,59.3 58.2,51.6 61.2,48.6 61.2,42.4 62.1,41.5 LCD.7
  Bottom Layer w0.3: R8.1 59,64.55 59,61.5 v1(60,60.5) 61.9,60.5 62.5,61.1 62.5,61.8 66,65.3 75.9,65.3 79.15,62.05 U4.40
RESET: EXP2.8
RS-: LCD.5 U4.42 | length 54.5
  Top Layer w0.3: v1(60.1,62.7) 59.6,62.7 56.8,59.9 56.8,51.2 60,48 60,41.6 62.1,39.5 LCD.5
  Bottom Layer w0.3: v1(60.1,62.7) 61.6,62.7 65.4,66.5 76.5,66.5 80.15,62.85 U4.42
RST-: LCD.8 U4.39 | length 44.8
  Top Layer w0.3: v1(61.3,59.4) 59.4,59.4 58.9,58.9 58.9,51.8 61.8,48.9 61.8,42.8 62.1,42.5 LCD.8
  Bottom Layer w0.3: v1(61.3,59.4) 61.9,59.4 63.2,60.7 63.2,61.6 66.3,64.7 75.6,64.7 78.65,61.65 U4.39
SCK: EXP2.2 R6.2 U2.4 | length 13.7
  Bottom Layer w0.3: EXP2.2 52.5,33.6 50.105,35.995 U2.4 50.105,38.905 51.7,40.5 R6.2
SCK-I: MSDX1.5 U2.16 U4.26 | length 63.7
  Top Layer w0.3: v1(34,52.5) 34,54.1 36.3,56.4 42.9,56.4 48.7,50.6 v1(48.5,50.4)
  Bottom Layer w0.3: MSDX1.5 33.3,53.2 v1(34,52.5) ; v1(48.5,50.4) 48.5,49.635 48.835,49.3 ; U2.16 48.835,49.3 ; U4.26 67.65,53.95 62,48.3 58.8,48.3 57.8,49.3 48.835,49.3
SCL: I2C.3 R3.1 U4.21 | length 22
  Bottom Layer w0.3: I2C.3 75.98,33.18 79.4,36.6 79.4,46 79.15,46.25 U4.21
SD-CS: EXP2.4 R6.3 U2.6 | length 17.7
  Bottom Layer w0.3: EXP2.4 49.96,33.74 47.565,36.135 U2.6 47.565,40.565 48.5,41.5 52.8,41.5 53,41.3 R6.3
SD-DET: EXP2.7 MSDX1.9 R11.1 | length 35.2
  Bottom Layer w0.3: MSDX1.9 34,46.8 37.8,43 37.8,41.4 38.55,40.65 R11.1 38.9,31.3 41.4,28.8 43.18,28.8 EXP2.7
SDA: I2C.2 R2.1 U4.22 | length 22.6
  Bottom Layer w0.3: I2C.2 78.65,36.91 R2.1 78.65,45.45 U4.22
WR-: LCD.6 U4.41 | length 51
  Top Layer w0.3: v1(61.3,61.6) 59.5,61.6 57.5,59.6 57.5,51.4 60.6,48.3 60.6,42 62.1,40.5 LCD.6
  Bottom Layer w0.3: v1@61.4,61.6 65.7,65.9 76.2,65.9 79.65,62.45 U4.41
pads on no net: B1.3 B1.4 B2.3 B2.4 LCD.26 LCD.27 LCD.28 LCD.29 MicroSD.0 MicroSD.1 MicroSD.8 MSDX1.1 MSDX1.8 MSDX2.1 MSDX2.8 U2.3 U2.9 U3.4 U3.9 U3.12

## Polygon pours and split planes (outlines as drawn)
GND on Bottom Layer "Bottom Layer-No Net" (solid, remove dead copper, pour order 13): 19,45.75 19,27.7 19.9,25.9 21.7,25 114.098,25 116.1,25.9 117,28 117,79 116.1,81.1 114.098,82 50.598,82 50.598,68 30.098,68 30.098,82 21.848,82 19.9,81.1 19,79 19,60.75 23,60.75 23,45.75
NetMicroSD_6 on Bottom Layer "Top Layer-No Net" (solid, remove dead copper, pour order 6): 31.5,69.5 49,69.5 49,76.5 47.5,76.5 47.5,78.1 49,78.1 49,82 31.5,82 31.5,78.1 32.9,78.1 32.9,76.5 31.5,76.5
+3.3V on Bottom Layer "Bottom Layer-No Net" (solid, remove dead copper, pour order 7): 61.4,38.1 78,38 78,49 76,49 75,50 75,52 75.5,52.5 75.5,53 68.5,53 62.6,47.1 61.4,47.1
+3.3V on Bottom Layer "Bottom Layer-No Net" (solid, remove dead copper, pour order 11): 59,36.5 77.5,36.5 78,37 78,51.8 77,52.8 68.3,52.8 68.25,52.75 62.5,47 62,47 59,47
GND on Top Layer "Bottom Layer-No Net" (solid, remove dead copper, pour order 9): 19,45.75 19,27.75 19.9,25.9 21.75,25 114,25 116.1,25.9 117,28 117,79 116.1,81.1 114,82 50.5,82 50.5,68 30,68 30,82 22,82 19.9,81.1 19,79 19,60.75 23,60.75 23,45.75
NetMicroSD_6 on Top Layer "Top Layer-No Net" (solid, remove dead copper, pour order 8): 31.5,69.5 31.5,76.5 33,76.5 33,78.1 31.5,78.1 31.5,82 49,82 49,78.2 47.5,78.2 47.5,76.5 49,76.5 49,69.5

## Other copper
Bottom Layer:
  text "TFTGLCD" at 71.2,77.6 h4
  text "V2.1" at 66.4,74.7 h4

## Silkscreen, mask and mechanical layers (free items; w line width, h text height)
Bottom Overlay:
  rectangle: 35.5,35.5 36,36
  rectangle: 33.5,35.5 34,36
  rectangle: 31.5,35.5 32,36
  rectangle: 29.5,35.5 30,36
  rectangle: 27.5,35.5 28,36
  rectangle: 27.5,37 28,37.5
  rectangle: 29.5,37 30,37.5
  rectangle: 31.5,37 32,37.5
  rectangle: 33.5,37 34,37.5
  rectangle: 35.5,37 36,37.5
  lines w0.1: 19,26 19,25 20,25 ; 19,81 19,82 20,82 ; 116,25 117,25 117,26 ; 116,82 117,82 117,81
  text "B1" at 90.2,73.3 h1.3 r270
  text "B2" at 92.8,73.3 h1.3 r270
  text "B3" at 95.4,73.3 h1.3 r270
  text "L" at 54.3,68.4 h1.5
  text "R" at 54.3,63.3 h1.5
  text "DIO" at 67,63.3 h1.5 r270
  text "GND" at 69.6,63.3 h1.5 r270
  text "+3.3V" at 72.1,63.3 h1.5 r270
  text "CLK" at 74.7,63.3 h1.5 r270
  text "KILL" at 27.1,38 h1.5 r270
  text "MOSI" at 31,38 h1.5 r270
  text "SD-CS" at 33,38 h1.5 r270
  text "SCK" at 35,38 h1.5 r270
  text "GND" at 27,31 h1.5 r270
  text "MISO" at 35,29.8 h1.5 r270
  text "SDDET" at 29,28 h1.5 r270
  text "LCD-CS" at 33,26.5 h1.5 r270
  text "+5V" at 70.1,26 h1.4 r270
  text "SDA" at 72.7,26 h1.4 r270
  text "SCL" at 75.3,26 h1.4 r270
  text "GND" at 77.8,26 h1.4 r270
Top Solder:
  rectangle: 47.55,78.1 48.95,80
  rectangle: 31.5,78.1 32.9,80
Bottom Solder:
  rectangle: 47.55,78.1 48.95,80
  rectangle: 31.5,78.1 32.9,80
OutBoard:
  lines w0.2: 19,28 ccw(c22,28) 22,25 114,25 ccw(c114,28) 117,28 117,79 ccw(c114,79) 114,82 50.5,82 50.5,68 46.5,68 46.5,69.5 49,69.5 49,76.5 47.5,76.5 47.5,78.1 49,78.1 49,82 31.5,82 31.5,78.1 32.9,78.1 32.9,76.5 31.5,76.5 31.5,69.5 43.5,69.5 43.5,68 30,68 30,82 22,82 ccw(c22,79) 19,79 19,60.6 23,60.6 23,45.8 19,45.8 19,28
